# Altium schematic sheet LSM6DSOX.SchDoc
size A4; Revision: V1.2; SheetNumber: 2; SheetTotal: 10
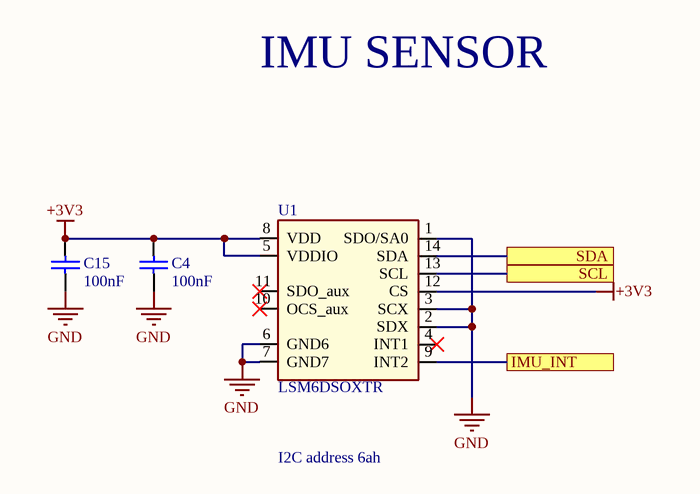
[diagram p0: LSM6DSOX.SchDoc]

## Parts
C4  value 100nF  [CAP-0402]  (hidden comment: GRM155R61H104KE19D)
C15  value 100nF  [CAP-0402]  (hidden comment: GRM155R61H104KE19D)
U1  LSM6DSOXTR  [VFLGA14]

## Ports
IMU_INT, SCL, SDA

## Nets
+3V3: C4.2 C15.2 U1.5(VDDIO) U1.8(VDD) U1.12(CS)
GND: C4.1 C15.1 U1.1(SDO/SA0) U1.2(SDX) U1.3(SCX) U1.6(GND6) U1.7(GND7)
IMU_INT: U1.9(INT2) ; port IMU_INT
SCL: U1.13(SCL) ; port SCL
SDA: U1.14(SDA) ; port SDA

Not connected (* = marked no-connect by the designer): U1 4(INT1)* 10(OCS_aux)* 11(SDO_aux)*

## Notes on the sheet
- IMU SENSOR
- I2C address 6ah

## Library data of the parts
C4 C15 = C0015-A.11: CAP CHIP 0402 100nF 50V X5R 10%; Manufacturer: Murata; Code Arduino: A5141
U1 = U0179-A.6: IMU ACCEL/GYRO I2C/SPI 14VFLGA; Manufacturer: STMicroelectronics; Max Supply Voltage: 3.6V; Min Supply Voltage: 1.7V; Code Arduino: U0179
